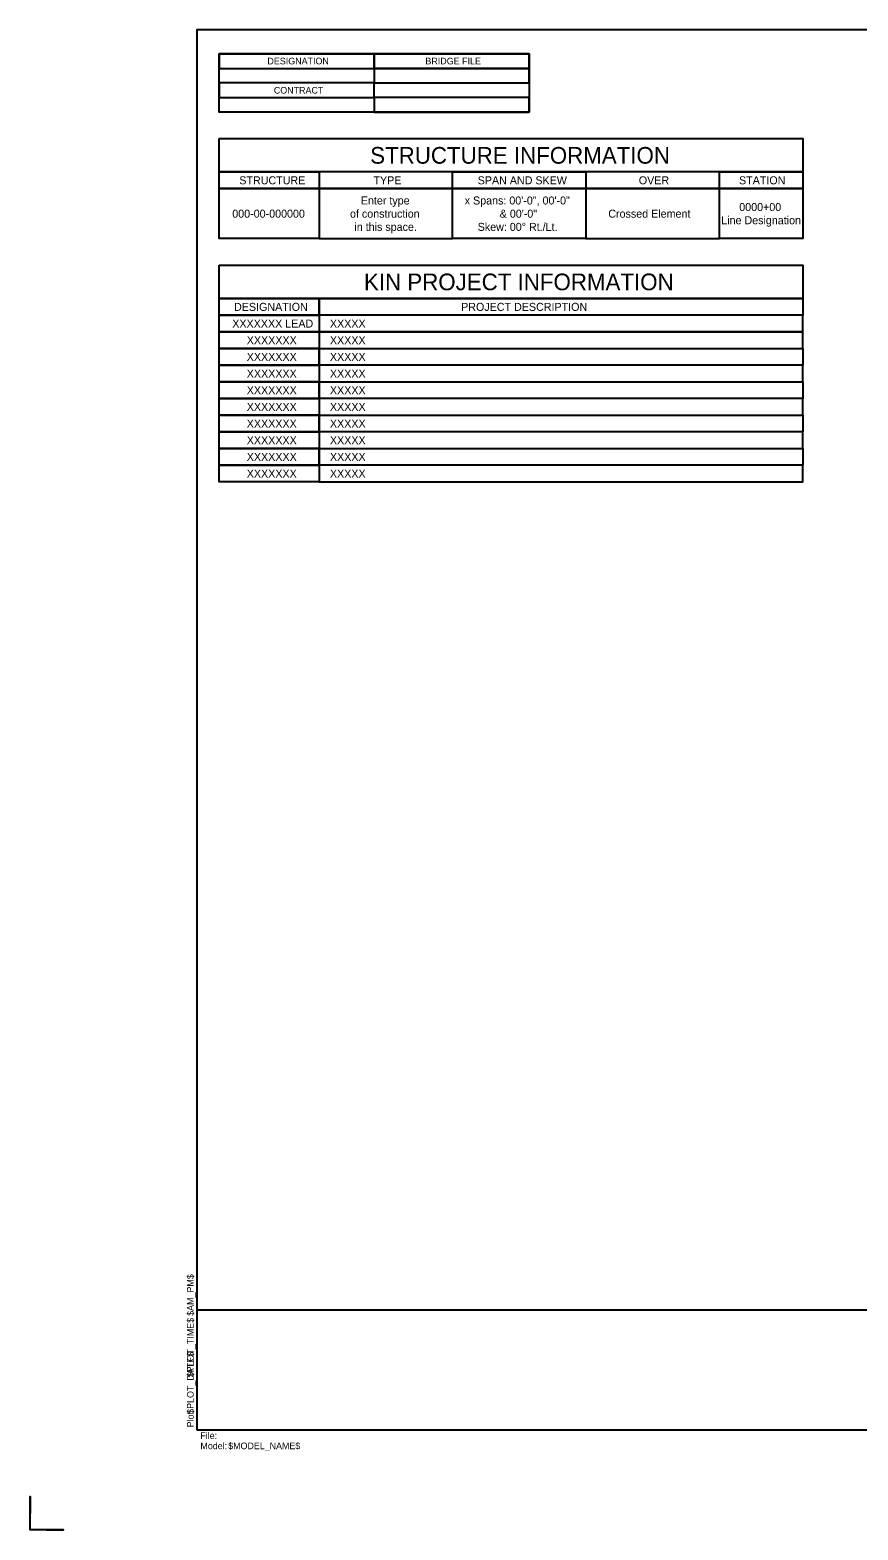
# Model space of a CAD drawing. Extents: x 0 to 3, y 0 to 2.
# Drawn here: x 0 to 1.034, y 0 to 1.875 of the extents above; entities that cross this region are included whole.
import ezdxf

# ---------------------------------------------------------------- set-up
doc = ezdxf.new("R2010")
doc.units = 0
for name, color, linetype in [('BD_Batch Plot Border', 7, 'Continuous'), ('BD_SHT', 7, 'Continuous'), ('BD_SHT_Frame', 7, 'Continuous'), ('BD_SHT_Numbering', 7, 'Continuous'), ('BD_SHT_Table Text', 7, 'Continuous'), ('BD_SHT_Text', 7, 'Continuous')]:
    doc.layers.add(name, color=color, linetype=linetype)

msp = doc.modelspace()

# ---------------------------------------------------------------- linework, layer by layer
at = {"layer": 'BD_Batch Plot Border'}
msp.add_lwpolyline([(0.0208, 0), (0.0417, 0), (0, 0), (0, 0.0417), (0, 0.0208)], dxfattribs=at)
at = {"layer": 'BD_SHT'}
for points in [[(0.2083, 0.125), (2.9167, 0.125), (2.9167, 1.875), (0.2083, 1.875)], [(0.2362, 1.8453), (0.6237, 1.8453), (0.6237, 1.7723), (0.2362, 1.7723)], [(0.2362, 1.827), (0.4299, 1.827), (0.4299, 1.8453), (0.2362, 1.8453)], [(0.4299, 1.827), (0.6237, 1.827), (0.6237, 1.8453), (0.4299, 1.8453)], [(0.2362, 1.827), (0.4299, 1.827), (0.4299, 1.8088), (0.2362, 1.8088)], [(0.6237, 1.827), (0.4299, 1.827), (0.4299, 1.8088), (0.6237, 1.8088)], [(0.4299, 1.8088), (0.2362, 1.8088), (0.2362, 1.7906), (0.4299, 1.7906)], [(0.4299, 1.8088), (0.6237, 1.8088), (0.6237, 1.7906), (0.4299, 1.7906)], [(0.2362, 1.7906), (0.4299, 1.7906), (0.4299, 1.7723), (0.2362, 1.7723)], [(0.6237, 1.7906), (0.4299, 1.7906), (0.4299, 1.7723), (0.6237, 1.7723)], [(0.2362, 1.7392), (0.9655, 1.7392), (0.9655, 1.6975), (0.2362, 1.6975)], [(0.2362, 1.6975), (0.3612, 1.6975), (0.3612, 1.6767), (0.2362, 1.6767)], [(0.3612, 1.6767), (0.5278, 1.6767), (0.5278, 1.6975), (0.3612, 1.6975)], [(0.5278, 1.6975), (0.6945, 1.6975), (0.6945, 1.6767), (0.5278, 1.6767)], [(0.6945, 1.6767), (0.8612, 1.6767), (0.8612, 1.6975), (0.6945, 1.6975)], [(0.8612, 1.6975), (0.9655, 1.6975), (0.9655, 1.6767), (0.8612, 1.6767)], [(0.2362, 1.6767), (0.3612, 1.6767), (0.3612, 1.6142), (0.2362, 1.6142)], [(0.3612, 1.6142), (0.5278, 1.6142), (0.5278, 1.6767), (0.3612, 1.6767)], [(0.5278, 1.6767), (0.6945, 1.6767), (0.6945, 1.6142), (0.5278, 1.6142)], [(0.6945, 1.6142), (0.8612, 1.6142), (0.8612, 1.6767), (0.6945, 1.6767)], [(0.8612, 1.6767), (0.9655, 1.6767), (0.9655, 1.6142), (0.8612, 1.6142)], [(0.2362, 1.581), (0.9655, 1.581), (0.9655, 1.5393), (0.2362, 1.5393)], [(0.2362, 1.5393), (0.3612, 1.5393), (0.3612, 1.5185), (0.2362, 1.5185)], [(0.3612, 1.5393), (0.9655, 1.5393), (0.9655, 1.5185), (0.3612, 1.5185)], [(0.2362, 1.5185), (0.3612, 1.5185), (0.3612, 1.4976), (0.2362, 1.4976)], [(0.3612, 1.4976), (0.9655, 1.4976), (0.9655, 1.5185), (0.3612, 1.5185)], [(0.2362, 1.4976), (0.3612, 1.4976), (0.3612, 1.4768), (0.2362, 1.4768)], [(0.9655, 1.4976), (0.3612, 1.4976), (0.3612, 1.4768), (0.9655, 1.4768)], [(0.2362, 1.4768), (0.3612, 1.4768), (0.3612, 1.456), (0.2362, 1.456)], [(0.3612, 1.4768), (0.9655, 1.4768), (0.9655, 1.456), (0.3612, 1.456)], [(0.2362, 1.456), (0.3612, 1.456), (0.3612, 1.4351), (0.2362, 1.4351)], [(0.9655, 1.456), (0.3612, 1.456), (0.3612, 1.4351), (0.9655, 1.4351)], [(0.2362, 1.4351), (0.3612, 1.4351), (0.3612, 1.4143), (0.2362, 1.4143)], [(0.3612, 1.4351), (0.9655, 1.4351), (0.9655, 1.4143), (0.3612, 1.4143)], [(0.2362, 1.4143), (0.3612, 1.4143), (0.3612, 1.3935), (0.2362, 1.3935)], [(0.9655, 1.4143), (0.3612, 1.4143), (0.3612, 1.3935), (0.9655, 1.3935)], [(0.2362, 1.3935), (0.3612, 1.3935), (0.3612, 1.3726), (0.2362, 1.3726)], [(0.3612, 1.3935), (0.9655, 1.3935), (0.9655, 1.3726), (0.3612, 1.3726)], [(0.2362, 1.3726), (0.3612, 1.3726), (0.3612, 1.3518), (0.2362, 1.3518)], [(0.9655, 1.3726), (0.3612, 1.3726), (0.3612, 1.3518), (0.9655, 1.3518)], [(0.2362, 1.3518), (0.3612, 1.3518), (0.3612, 1.331), (0.2362, 1.331)], [(0.3612, 1.3518), (0.9655, 1.3518), (0.9655, 1.331), (0.3612, 1.331)], [(0.2362, 1.331), (0.3612, 1.331), (0.3612, 1.3101), (0.2362, 1.3101)], [(0.9655, 1.331), (0.3612, 1.331), (0.3612, 1.3101), (0.9655, 1.3101)]]:
    msp.add_lwpolyline(points, close=True, dxfattribs=at)
msp.add_lwpolyline([(0.2083, 0.275), (0.2083, 0.275), (2.9167, 0.275)], dxfattribs=at)
at = {"layer": 'BD_SHT_Frame'}
msp.add_lwpolyline([(0.2083, 0.125), (2.9167, 0.125), (2.9167, 1.875), (0.2083, 1.875)], close=True, dxfattribs=at)

# ---------------------------------------------------------------- texts
at = {"layer": 'BD_SHT_Numbering'}
for s, height, p in [('$AM_PM$', 0.00833, (0.2045, 0.2677)), ('$PLOT_TIME$', 0.008333, (0.2045, 0.1909)), ('$PLOT_DATE$', 0.008333, (0.2045, 0.1452)), ('Plot:', 0.00833, (0.2045, 0.1283))]:
    msp.add_text(s, height=height, rotation=90, dxfattribs=at).set_placement(p)
at = {"layer": 'BD_SHT_Table Text'}
for s, height, p in [('STRUCTURE INFORMATION', 0.020833, (0.425, 1.7079)), ('000-00-000000', 0.01, (0.2527, 1.6404)), ('of construction', 0.01, (0.3998, 1.6404)), ('Enter type', 0.01, (0.4133, 1.6569)), ('x Spans: 00\'-0", 00\'-0"', 0.01, (0.5431, 1.6569)), ('& 00\'-0"', 0.01, (0.5868, 1.6404)), ('Crossed Element', 0.01, (0.7225, 1.6404)), ('0000+00', 0.01, (0.8861, 1.6487)), ('in this space.', 0.01, (0.4053, 1.6239)), ('Skew: 00° Rt./Lt.', 0.01, (0.5593, 1.6239)), ('Line Designation', 0.01, (0.8636, 1.6322)), ('KIN PROJECT INFORMATION', 0.020833, (0.4172, 1.5497))]:
    msp.add_text(s, height=height, dxfattribs=at).set_placement(p)
at = {"layer": 'BD_SHT_Text'}
for s, height, p in [('DESIGNATION', 0.008333, (0.2966, 1.832)), ('BRIDGE FILE', 0.008333, (0.494, 1.832)), ('CONTRACT', 0.00833, (0.3046, 1.7955)), ('STRUCTURE', 0.01, (0.2615, 1.6821)), ('TYPE', 0.01, (0.4291, 1.6821)), ('SPAN AND SKEW', 0.01, (0.5593, 1.6821)), ('OVER', 0.01, (0.7606, 1.6821)), ('STATION', 0.01, (0.8858, 1.6821)), ('DESIGNATION', 0.01, (0.2549, 1.5239)), ('PROJECT DESCRIPTION', 0.01, (0.5386, 1.5239)), ('XXXXXXX LEAD', 0.01, (0.2527, 1.503)), ('XXXXX', 0.01, (0.3747, 1.503)), ('XXXXXXX', 0.01, (0.2708, 1.4822)), ('XXXXX', 0.01, (0.3747, 1.4822)), ('XXXXXXX', 0.01, (0.2708, 1.4614)), ('XXXXX', 0.01, (0.3747, 1.4614)), ('XXXXXXX', 0.01, (0.2708, 1.4405)), ('XXXXX', 0.01, (0.3747, 1.4405)), ('XXXXXXX', 0.01, (0.2708, 1.4197)), ('XXXXX', 0.01, (0.3747, 1.4197)), ('XXXXXXX', 0.01, (0.2708, 1.3989)), ('XXXXX', 0.01, (0.3747, 1.3989)), ('XXXXXXX', 0.01, (0.2708, 1.378)), ('XXXXX', 0.01, (0.3747, 1.378)), ('XXXXXXX', 0.01, (0.2708, 1.3572)), ('XXXXX', 0.01, (0.3747, 1.3572)), ('XXXXXXX', 0.01, (0.2708, 1.3364)), ('XXXXX', 0.01, (0.3747, 1.3364)), ('XXXXXXX', 0.01, (0.2708, 1.3155)), ('XXXXX', 0.01, (0.3747, 1.3155)), ('File:', 0.0083, (0.2128, 0.1139)), ('Model: ', 0.0083, (0.2129, 0.101)), ('$MODEL_NAME$', 0.0083, (0.2476, 0.101))]:
    msp.add_text(s, height=height, dxfattribs=at).set_placement(p)

doc.saveas('drawing.dxf')
